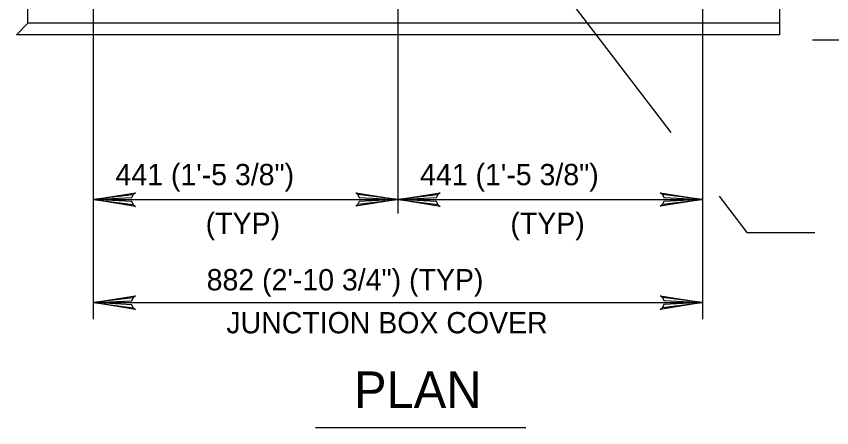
# Model space of a CAD drawing. Extents: x 638455 to 640199, y 298558 to 299152.
# Drawn here: x 638610.5 to 638739.1, y 298862.9 to 298927.7 of the extents above; entities that cross this region are included whole.
import ezdxf

# ---------------------------------------------------------------- set-up
doc = ezdxf.new("R2010")
doc.units = 0
for name, color, linetype in [('1', 7, 'Continuous'), ('2', 7, 'Continuous'), ('3', 7, 'Continuous')]:
    doc.layers.add(name, color=color, linetype=linetype)

msp = doc.modelspace()

# ---------------------------------------------------------------- linework, layer by layer
at = {"layer": '2'}
for p, q in [((638670.65, 298967.95), (638670.65, 298905.86)), ((638672.9, 298962.83), (638713.69, 298909.4)), ((638612.27, 298926.64), (638612.27, 298937.65)), ((638622.59, 298934.11), (638622.59, 298879.96)), ((638718.71, 298934.11), (638718.71, 298879.96)), ((638612.27, 298926.64), (638610.47, 298924.83)), ((638736.06, 298924.03), (638814.78, 298924.03)), ((638670.65, 298905.86), (638670.65, 298896.62)), ((638622.59, 298898.85), (638670.65, 298898.85)), ((638670.65, 298898.85), (638718.71, 298898.85)), ((638721.33, 298899.39), (638725.7, 298893.67)), ((638725.7, 298893.67), (638736.42, 298893.67)), ((638622.59, 298882.59), (638718.71, 298882.59))]:
    msp.add_line(p, q, dxfattribs=at)
for points in [[(638610.47, 299045.2), (638730.83, 299045.2), (638730.83, 298924.83), (638610.47, 298924.83)], [(638730.83, 298926.64), (638612.27, 298926.64)], [(638628.92, 298898.05), (638628.69, 298898.51), (638622.59, 298898.85), (638628.92, 298898.05), (638629.25, 298897.77), (638622.59, 298898.85), (638628.68, 298899.15), (638628.9, 298899.6), (638622.59, 298898.85), (638629.25, 298899.9), (638628.9, 298899.6)], [(638664.32, 298899.64), (638664.56, 298899.18), (638670.65, 298898.85), (638664.32, 298899.64), (638664, 298899.92), (638670.65, 298898.85), (638664.56, 298898.55), (638664.34, 298898.09), (638670.65, 298898.85), (638664, 298897.79), (638664.34, 298898.09)], [(638676.98, 298898.05), (638676.74, 298898.51), (638670.65, 298898.85), (638676.98, 298898.05), (638677.3, 298897.77), (638670.65, 298898.85), (638676.74, 298899.15), (638676.96, 298899.6), (638670.65, 298898.85), (638677.3, 298899.9), (638676.96, 298899.6)], [(638712.37, 298899.64), (638712.61, 298899.18), (638718.71, 298898.85), (638712.37, 298899.64), (638712.05, 298899.92), (638718.71, 298898.85), (638712.62, 298898.55), (638712.39, 298898.09), (638718.71, 298898.85), (638712.05, 298897.79), (638712.39, 298898.09)], [(638628.92, 298881.79), (638628.69, 298882.25), (638622.59, 298882.59), (638628.92, 298881.79), (638629.25, 298881.51), (638622.59, 298882.59), (638628.68, 298882.89), (638628.9, 298883.34), (638622.59, 298882.59), (638629.25, 298883.64), (638628.9, 298883.34)], [(638712.37, 298883.38), (638712.61, 298882.92), (638718.71, 298882.59), (638712.37, 298883.38), (638712.05, 298883.66), (638718.71, 298882.59), (638712.62, 298882.29), (638712.39, 298881.83), (638718.71, 298882.59), (638712.05, 298881.53), (638712.39, 298881.83)]]:
    msp.add_lwpolyline(points, dxfattribs=at)
at = {"layer": '3'}
msp.add_line((638657.67, 298862.88), (638690.84, 298862.88), dxfattribs=at)

# ---------------------------------------------------------------- texts
at = {"layer": '1'}
for p in [(638640.34, 298893.41), (638688.4, 298893.41)]:
    msp.add_text('(TYP)', height=3.36, dxfattribs=at).set_placement(p)
at = {"layer": '3'}
for s, height, p in [('441 (1\'-5 3/8")', 3.36, (638626.11, 298901.1)), ('441 (1\'-5 3/8")', 3.36, (638674.16, 298901.1)), ('882 (2\'-10 3/4") (TYP)', 3.36, (638640.49, 298884.52)), ('JUNCTION BOX COVER', 3.36, (638643.6, 298877.75)), ('PLAN', 5.76, (638663.73, 298865.98))]:
    msp.add_text(s, height=height, dxfattribs=at).set_placement(p)

doc.saveas('drawing.dxf')
